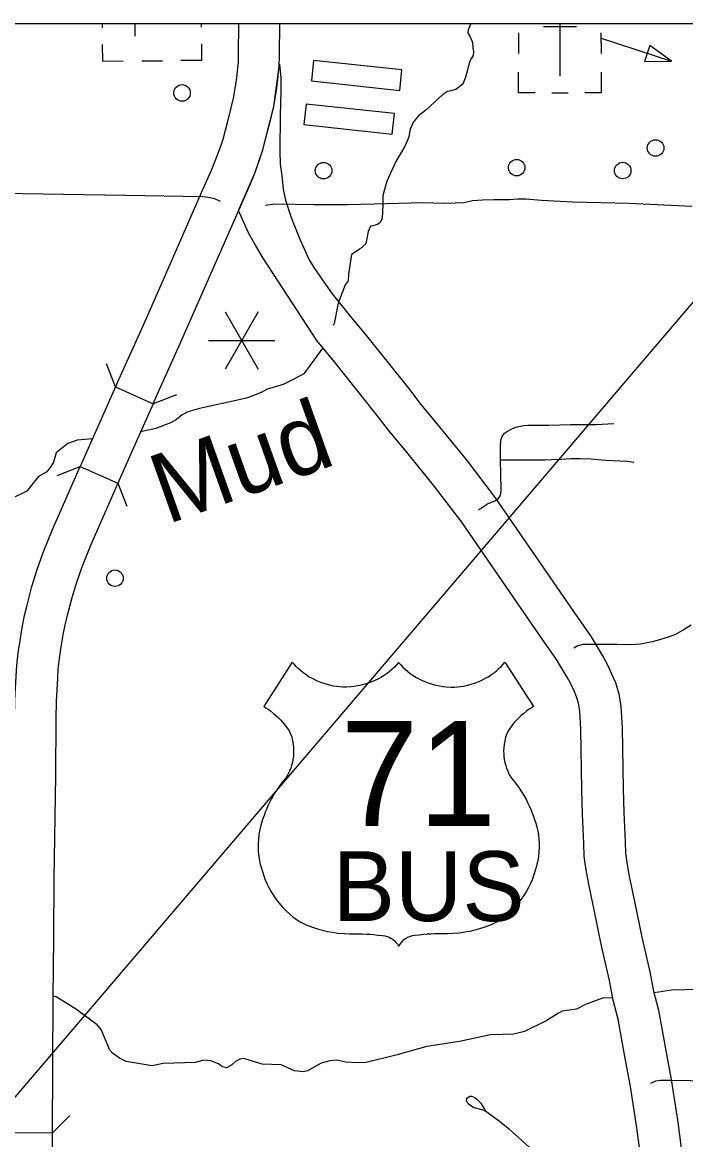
# Model space of a CAD drawing. Extents: x 1382482 to 1385815, y 1168351 to 1170484.
# Drawn here: x 1384330.9 to 1384491.5, y 1169309.6 to 1169580 of the extents above; entities that cross this region are included whole.
import ezdxf

# ---------------------------------------------------------------- set-up
doc = ezdxf.new("R2010")
doc.units = 0
for name, color, linetype in [('10', 7, 'Continuous'), ('15', 7, 'Continuous'), ('22', 7, 'Continuous'), ('35', 7, 'Continuous'), ('37', 7, 'Continuous'), ('48', 7, 'Continuous'), ('57', 7, 'Continuous'), ('Default', 7, 'Continuous'), ('R_Dimension', 7, 'Continuous'), ('R_No Plot', 7, 'Continuous')]:
    doc.layers.add(name, color=color, linetype=linetype)

msp = doc.modelspace()

# ---------------------------------------------------------------- linework, layer by layer
at = {"layer": '10'}
for points in [[(1384383.23, 1169534.42), (1384387.14, 1169543.49), (1384389.03, 1169548.84), (1384391.74, 1169559.61), (1384393.11, 1169569.87), (1384393.48, 1169566.57), (1384393.48, 1169563.3), (1384393.33, 1169557.39), (1384393.24, 1169548.76), (1384393.33, 1169545.62), (1384393.68, 1169542.87), (1384394.04, 1169539.57), (1384394.61, 1169536.9), (1384395.96, 1169532.72), (1384398.07, 1169527.54), (1384400.3, 1169522.48), (1384401.48, 1169520.67), (1384403.64, 1169517.52), (1384405.93, 1169514.26), (1384409.6, 1169509.67), (1384409.86, 1169509.35)], [(1384402.15, 1169502.98), (1384389.22, 1169522.94), (1384387.39, 1169525.88), (1384385.69, 1169528.89), (1384384.49, 1169531.54), (1384383.23, 1169534.42)], [(1384409.86, 1169509.35), (1384414.2, 1169504.11), (1384424.35, 1169491.44), (1384427.36, 1169487.53), (1384432.01, 1169481.88), (1384438.54, 1169473.85), (1384445.39, 1169464.94), (1384464.29, 1169437.42), (1384468.6, 1169431.26), (1384471.58, 1169426.28), (1384472.51, 1169424.53), (1384473.55, 1169422.34), (1384474.48, 1169420.2), (1384475.27, 1169417.52), (1384475.8, 1169414.44), (1384476.06, 1169409.29), (1384476.3, 1169394.54), (1384476.49, 1169388.81), (1384476.82, 1169381.66), (1384476.91, 1169378.96), (1384477.11, 1169377.28), (1384477.38, 1169375.76), (1384477.74, 1169373.73), (1384478.45, 1169370.33), (1384479.08, 1169367.26), (1384480.89, 1169358.63), (1384482.81, 1169350.2), (1384483.71, 1169345.55), (1384484.87, 1169340.95), (1384485.71, 1169336.52), (1384486.77, 1169330.7), (1384487.98, 1169324.16), (1384489.59, 1169313.88), (1384490.38, 1169307.55)], [(1384480.43, 1169306.53), (1384479.68, 1169312.48), (1384478.12, 1169322.48), (1384476.94, 1169328.9), (1384475.88, 1169334.69), (1384475.1, 1169338.8), (1384473.95, 1169343.38), (1384473.03, 1169348.13), (1384471.12, 1169356.49), (1384469.28, 1169365.24), (1384468.66, 1169368.31), (1384467.93, 1169371.82), (1384467.53, 1169374.02), (1384467.21, 1169375.85), (1384466.93, 1169378.2), (1384466.83, 1169381.26), (1384466.5, 1169388.41), (1384466.3, 1169394.29), (1384466.06, 1169408.96), (1384465.84, 1169413.34), (1384465.51, 1169415.25), (1384465.06, 1169416.79), (1384464.45, 1169418.2), (1384463.57, 1169420.04), (1384462.87, 1169421.37), (1384460.2, 1169425.82), (1384456.07, 1169431.72), (1384437.3, 1169459.06), (1384430.7, 1169467.64), (1384424.27, 1169475.54), (1384419.53, 1169481.31), (1384416.49, 1169485.27), (1384406.45, 1169497.79), (1384402.15, 1169502.98)]]:
    msp.add_lwpolyline(points, dxfattribs=at)
at = {"layer": '15'}
for points in [[(1384383.23, 1169579.7), (1384383.15, 1169572.16), (1384383.11, 1169570.02), (1384383.08, 1169569.78), (1384382.82, 1169567.21), (1384382.53, 1169564.96), (1384381.94, 1169561.64), (1384381.39, 1169559.29), (1384380.59, 1169555.99), (1384379.43, 1169551.65), (1384378.97, 1169550.2), (1384378.17, 1169548.07), (1384377.84, 1169547.17), (1384376.57, 1169544.12), (1384374.2, 1169538.72), (1384364.4, 1169516.4), (1384359.63, 1169505.56), (1384354.2, 1169493.43), (1384353.44, 1169491.74), (1384362.57, 1169487.66)], [(1384362.57, 1169487.66), (1384363.32, 1169489.34), (1384368.77, 1169501.51), (1384373.56, 1169512.38), (1384383.36, 1169534.7), (1384385.77, 1169540.19), (1384387.14, 1169543.49), (1384387.54, 1169544.57), (1384388.42, 1169546.94), (1384389.03, 1169548.84), (1384390.28, 1169553.53), (1384391.11, 1169556.97), (1384391.74, 1169559.61), (1384392.42, 1169563.44), (1384392.76, 1169566.08), (1384393.01, 1169568.65), (1384393.09, 1169569.27), (1384393.15, 1169572.01), (1384393.23, 1169579.7)], [(1384353.44, 1169491.74), (1384349.32, 1169482.51), (1384344.9, 1169472.5)], [(1384362.57, 1169487.66), (1384358.46, 1169478.45), (1384354.05, 1169468.46)], [(1384338.14, 1169311.22), (1384328.14, 1169311.27), (1384328.32, 1169344.04), (1384328.45, 1169358.54), (1384328.5, 1169373.03), (1384328.95, 1169397.67), (1384329.04, 1169411.52), (1384329.08, 1169416.04), (1384329.38, 1169421.73), (1384329.53, 1169424.34), (1384329.9, 1169427.4), (1384330.37, 1169430.41), (1384330.88, 1169433.52), (1384331.42, 1169436.43), (1384332, 1169438.62), (1384333.21, 1169443.46), (1384334.5, 1169447.58), (1384335.93, 1169451.66), (1384338.18, 1169457.24), (1384342.61, 1169467.31), (1384344.9, 1169472.5)], [(1384344.9, 1169472.5), (1384354.05, 1169468.46), (1384351.76, 1169463.28), (1384347.39, 1169453.36), (1384345.29, 1169448.15), (1384344, 1169444.43), (1384342.84, 1169440.75), (1384341.69, 1169436.12), (1384341.18, 1169434.23), (1384340.73, 1169431.79), (1384340.24, 1169428.83), (1384339.81, 1169426.03), (1384339.49, 1169423.46), (1384339.37, 1169421.19), (1384339.08, 1169415.73), (1384339.04, 1169411.44), (1384338.95, 1169397.54), (1384338.5, 1169372.92), (1384338.45, 1169358.48), (1384338.32, 1169343.96), (1384338.14, 1169311.22)], [(1384338.14, 1169311.22), (1384338.09, 1169302.22)]]:
    msp.add_lwpolyline(points, dxfattribs=at)
at = {"layer": '22'}
for points in [[(1384421.98, 1169425.08), (1384421.46, 1169424.49), (1384420.95, 1169423.97), (1384420.38, 1169423.43), (1384419.77, 1169422.91), (1384419.17, 1169422.44), (1384418.45, 1169421.94), (1384417.67, 1169421.45), (1384416.79, 1169420.97), (1384415.67, 1169420.45), (1384414.81, 1169420.12), (1384413.84, 1169419.8), (1384412.95, 1169419.57), (1384412.13, 1169419.4), (1384411.26, 1169419.27), (1384410.47, 1169419.18), (1384409.38, 1169419.13), (1384408.5, 1169419.14), (1384407.73, 1169419.19), (1384406.99, 1169419.27), (1384406.25, 1169419.38), (1384405.32, 1169419.57), (1384404.45, 1169419.8), (1384403.4, 1169420.14), (1384402.51, 1169420.49), (1384401.7, 1169420.86), (1384400.96, 1169421.25), (1384400.27, 1169421.65), (1384399.51, 1169422.16), (1384398.81, 1169422.67), (1384398.2, 1169423.17), (1384397.69, 1169423.62), (1384397.17, 1169424.12), (1384396.66, 1169424.66), (1384396.25, 1169425.13), (1384389.32, 1169414.43), (1384389.82, 1169414.13), (1384390.41, 1169413.75), (1384390.96, 1169413.35), (1384391.71, 1169412.77), (1384392.3, 1169412.26), (1384392.83, 1169411.77), (1384393.36, 1169411.22), (1384393.91, 1169410.61), (1384394.31, 1169410.14), (1384394.7, 1169409.64), (1384395.09, 1169409.09), (1384395.47, 1169408.51), (1384395.83, 1169407.83), (1384396.1, 1169406.99), (1384396.3, 1169406.16), (1384396.45, 1169405.28), (1384396.54, 1169404.46), (1384396.56, 1169403.67), (1384396.54, 1169402.93), (1384396.5, 1169402.33), (1384396.4, 1169401.6), (1384396.26, 1169400.91), (1384396.07, 1169400.17), (1384395.86, 1169399.52), (1384395.58, 1169398.79), (1384395.12, 1169397.85), (1384394.66, 1169397.11), (1384394.11, 1169396.44), (1384393.43, 1169395.57), (1384392.88, 1169394.8), (1384392.37, 1169394.04), (1384391.89, 1169393.29), (1384391.5, 1169392.62), (1384391.15, 1169391.99), (1384390.76, 1169391.24), (1384390.34, 1169390.37), (1384389.97, 1169389.52), (1384389.71, 1169388.88), (1384389.4, 1169388.07), (1384389.06, 1169387.07), (1384388.8, 1169386.24), (1384388.55, 1169385.34), (1384388.31, 1169384.28), (1384388.16, 1169383.35), (1384388.05, 1169382.37), (1384387.98, 1169381.31), (1384387.98, 1169380.31), (1384388.02, 1169379.33), (1384388.14, 1169378.18), (1384388.32, 1169377.09), (1384388.5, 1169376.27), (1384388.69, 1169375.55), (1384388.93, 1169374.73), (1384389.24, 1169373.71), (1384389.7, 1169372.48), (1384390.09, 1169371.57), (1384390.55, 1169370.64), (1384391.05, 1169369.72), (1384391.7, 1169368.67), (1384392.38, 1169367.7), (1384393.03, 1169366.86), (1384393.77, 1169366), (1384394.73, 1169365.01), (1384395.54, 1169364.26), (1384396.38, 1169363.56)], [(1384421.98, 1169425.08), (1384422.51, 1169424.49), (1384423.01, 1169423.97), (1384423.58, 1169423.43), (1384424.2, 1169422.91), (1384424.8, 1169422.44), (1384425.52, 1169421.94), (1384426.29, 1169421.45), (1384427.18, 1169420.97), (1384428.3, 1169420.45), (1384429.16, 1169420.12), (1384430.13, 1169419.8), (1384431.02, 1169419.57), (1384431.84, 1169419.4), (1384432.7, 1169419.27), (1384433.5, 1169419.18), (1384434.59, 1169419.13), (1384435.47, 1169419.14), (1384436.24, 1169419.19), (1384436.97, 1169419.27), (1384437.71, 1169419.38), (1384438.65, 1169419.57), (1384439.51, 1169419.8), (1384440.57, 1169420.14), (1384441.46, 1169420.49), (1384442.27, 1169420.86), (1384443.01, 1169421.25), (1384443.69, 1169421.65), (1384444.46, 1169422.16), (1384445.16, 1169422.67), (1384445.77, 1169423.17), (1384446.28, 1169423.62), (1384446.8, 1169424.12), (1384447.31, 1169424.66), (1384447.72, 1169425.13), (1384454.64, 1169414.43), (1384454.15, 1169414.13), (1384453.56, 1169413.75), (1384453, 1169413.35), (1384452.26, 1169412.77), (1384451.67, 1169412.26), (1384451.14, 1169411.77), (1384450.6, 1169411.22), (1384450.05, 1169410.61), (1384449.66, 1169410.14), (1384449.27, 1169409.64), (1384448.88, 1169409.09), (1384448.49, 1169408.51), (1384448.14, 1169407.83), (1384447.87, 1169406.99), (1384447.67, 1169406.16), (1384447.51, 1169405.28), (1384447.43, 1169404.46), (1384447.4, 1169403.67), (1384447.42, 1169402.93), (1384447.47, 1169402.33), (1384447.57, 1169401.6), (1384447.7, 1169400.91), (1384447.9, 1169400.17), (1384448.11, 1169399.52), (1384448.39, 1169398.79), (1384448.84, 1169397.85), (1384449.3, 1169397.11), (1384449.86, 1169396.44), (1384450.54, 1169395.57), (1384451.09, 1169394.8), (1384451.6, 1169394.04), (1384452.07, 1169393.29), (1384452.47, 1169392.62), (1384452.82, 1169391.99), (1384453.2, 1169391.24), (1384453.62, 1169390.37), (1384454, 1169389.52), (1384454.26, 1169388.88), (1384454.56, 1169388.07), (1384454.9, 1169387.07), (1384455.17, 1169386.24), (1384455.42, 1169385.34), (1384455.65, 1169384.28), (1384455.81, 1169383.35), (1384455.92, 1169382.37), (1384455.98, 1169381.31), (1384455.99, 1169380.31), (1384455.94, 1169379.33), (1384455.82, 1169378.18), (1384455.65, 1169377.09), (1384455.47, 1169376.27), (1384455.28, 1169375.55), (1384455.04, 1169374.73), (1384454.72, 1169373.71), (1384454.27, 1169372.48), (1384453.87, 1169371.57), (1384453.42, 1169370.64), (1384452.91, 1169369.72), (1384452.26, 1169368.67), (1384451.59, 1169367.7), (1384450.94, 1169366.86), (1384450.19, 1169366), (1384449.24, 1169365.01), (1384448.42, 1169364.26), (1384447.59, 1169363.56)], [(1384396.38, 1169363.56), (1384397.25, 1169362.9), (1384398.29, 1169362.22), (1384399.6, 1169361.63), (1384401.13, 1169361.04), (1384402.38, 1169360.64), (1384403.51, 1169360.32), (1384404.78, 1169360.03), (1384405.98, 1169359.81), (1384407.26, 1169359.63), (1384408.88, 1169359.49), (1384410.12, 1169359.45), (1384411.18, 1169359.46), (1384412.21, 1169359.45), (1384413.24, 1169359.41), (1384414.22, 1169359.37), (1384415.07, 1169359.31), (1384415.91, 1169359.24), (1384416.99, 1169359.13), (1384418.04, 1169358.99), (1384418.67, 1169358.91), (1384419.19, 1169358.8), (1384419.82, 1169358.54), (1384420.18, 1169358.34), (1384420.5, 1169358.14), (1384420.93, 1169357.79), (1384421.34, 1169357.37), (1384421.68, 1169356.94), (1384421.98, 1169356.44)], [(1384447.59, 1169363.56), (1384446.72, 1169362.9), (1384445.68, 1169362.22), (1384444.37, 1169361.63), (1384442.84, 1169361.04), (1384441.58, 1169360.64), (1384440.46, 1169360.32), (1384439.18, 1169360.03), (1384437.99, 1169359.81), (1384436.7, 1169359.63), (1384435.09, 1169359.49), (1384433.85, 1169359.45), (1384432.79, 1169359.46), (1384431.76, 1169359.45), (1384430.73, 1169359.41), (1384429.75, 1169359.37), (1384428.89, 1169359.31), (1384428.05, 1169359.24), (1384426.98, 1169359.13), (1384425.93, 1169358.99), (1384425.3, 1169358.91), (1384424.78, 1169358.8), (1384424.15, 1169358.54), (1384423.78, 1169358.34), (1384423.47, 1169358.14), (1384423.04, 1169357.79), (1384422.63, 1169357.37), (1384422.29, 1169356.94), (1384421.98, 1169356.44)]]:
    msp.add_lwpolyline(points, dxfattribs=at)
at = {"layer": '35'}
for points in [[(1384439.49, 1169579.7), (1384438.84, 1169578.15), (1384438.71, 1169577.41), (1384439.27, 1169576.43), (1384439.87, 1169575.09), (1384439.96, 1169573.69), (1384440.1, 1169572.9), (1384440.01, 1169571.93), (1384439.5, 1169571.04), (1384439.22, 1169570.56), (1384438.21, 1169566.71), (1384437.5, 1169564.99), (1384435.83, 1169563.7), (1384434.66, 1169563.37), (1384433.78, 1169563.19), (1384432.62, 1169562.39), (1384430.71, 1169560.77), (1384429.55, 1169559.61), (1384428.53, 1169558.72), (1384426.76, 1169557.37), (1384425.56, 1169555.93), (1384424.81, 1169554.12), (1384424.44, 1169552.35), (1384424.23, 1169551.59), (1384423.44, 1169549.82), (1384421.3, 1169546.29), (1384419.12, 1169541.5), (1384418.14, 1169538.06), (1384418.19, 1169536.24), (1384418.17, 1169536.13)], [(1384418.19, 1169536.24), (1384418.05, 1169533.65), (1384417.91, 1169532.44), (1384417.49, 1169531.51), (1384416.84, 1169531.04), (1384415.77, 1169530.76), (1384415.21, 1169530.62), (1384414.61, 1169529.37), (1384414.07, 1169526.36), (1384412.66, 1169525.14), (1384410.61, 1169523.79), (1384409.87, 1169519.06), (1384409.73, 1169517.43), (1384409.03, 1169516.45), (1384407.38, 1169512.04), (1384406.37, 1169507.12), (1384406.12, 1169506.59)], [(1384403.63, 1169501.2), (1384399.03, 1169494.94), (1384396.31, 1169493.43), (1384394.04, 1169492.36), (1384390.18, 1169491.2)], [(1384390.18, 1169491.2), (1384388.74, 1169490.41), (1384385.39, 1169489.1), (1384383.36, 1169488.64), (1384373.82, 1169486.5), (1384370.94, 1169485.76), (1384369.59, 1169484.97), (1384368.24, 1169483.9), (1384366.76, 1169483.06), (1384363.22, 1169481.72), (1384359.54, 1169480.87)], [(1384347.86, 1169479.21), (1384344.15, 1169478.84), (1384341.94, 1169478.1), (1384340.29, 1169476.77), (1384339.07, 1169475.82), (1384338.47, 1169473.57), (1384337.82, 1169472.53), (1384336.84, 1169471.22), (1384334.82, 1169470.09), (1384333.42, 1169468.4), (1384331.95, 1169466.52), (1384328.35, 1169464.72)], [(1384494.37, 1169345.96), (1384488.05, 1169345.82), (1384483.8, 1169345.19)], [(1384460.69, 1169340.25), (1384457.87, 1169338.47), (1384452.46, 1169335.79), (1384449.91, 1169335.14), (1384444.22, 1169335.02), (1384436.69, 1169333.36), (1384428.81, 1169332.15), (1384421.29, 1169330.1), (1384414.12, 1169328.33), (1384412.01, 1169328.19), (1384409.22, 1169328.41), (1384407.06, 1169328.88), (1384405.31, 1169328.71), (1384403.24, 1169328.13), (1384399.94, 1169326.31), (1384398.87, 1169326.02), (1384396.76, 1169326.25), (1384393.56, 1169327.74), (1384388.93, 1169327.87), (1384384.54, 1169329.28), (1384383.58, 1169329.11), (1384382.51, 1169328.51), (1384381.6, 1169327.7), (1384380.33, 1169327.01), (1384379.37, 1169327.28), (1384378.37, 1169328), (1384376.49, 1169328.7), (1384374.74, 1169328.89), (1384372.79, 1169328.32), (1384365.01, 1169328.06), (1384362.31, 1169327.52), (1384356, 1169328.56), (1384354.4, 1169329.35), (1384352.76, 1169330.53), (1384352.08, 1169331.25), (1384349.97, 1169336.27), (1384349.05, 1169337.43), (1384344, 1169341.15), (1384339.08, 1169344.19), (1384338.32, 1169344.38)], [(1384473.86, 1169343.83), (1384471.56, 1169343.91), (1384467.21, 1169342.37), (1384465.02, 1169341.2), (1384461.56, 1169340.7), (1384460.69, 1169340.25)]]:
    msp.add_lwpolyline(points, dxfattribs=at)
at = {"layer": '37'}
for points in [[(1384353.44, 1169491.74), (1384351.3, 1169497.34)], [(1384368.18, 1169489.8), (1384362.57, 1169487.66)], [(1384339.3, 1169470.34), (1384344.9, 1169472.5)], [(1384354.05, 1169468.46), (1384356.21, 1169462.87)], [(1384342.4, 1169315.44), (1384338.14, 1169311.22)]]:
    msp.add_lwpolyline(points, dxfattribs=at)
at = {"layer": '48'}
for p, q in [((1384387.99, 1169509.89), (1384379.99, 1169496.03)), ((1384379.99, 1169509.89), (1384387.99, 1169496.03)), ((1384375.99, 1169502.96), (1384391.99, 1169502.96))]:
    msp.add_line(p, q, dxfattribs=at)
at = {"layer": '57'}
for p, q in [((1384350.22, 1169579.7), (1384350.23, 1169578.6)), ((1384358.25, 1169576.64), (1384358.23, 1169579.7)), ((1384374.23, 1169578.77), (1384374.23, 1169579.7)), ((1384457.02, 1169578.92), (1384465.05, 1169578.92)), ((1384461.02, 1169579.7), (1384461.02, 1169566.92)), ((1384451.02, 1169577.39), (1384451.02, 1169572.39)), ((1384471.02, 1169574.92), (1384471.02, 1169577.39)), ((1384461.02, 1169574.92), (1384461.02, 1169574.92)), ((1384461.02, 1169574.92), (1384461.02, 1169574.92)), ((1384471.02, 1169574.92), (1384471.02, 1169572.39)), ((1384359.83, 1169570.65), (1384364.83, 1169570.68)), ((1384401.4, 1169570.75), (1384400.86, 1169565.78)), ((1384422.78, 1169568.44), (1384401.4, 1169570.75)), ((1384422.24, 1169563.47), (1384422.78, 1169568.44)), ((1384400.86, 1169565.78), (1384422.24, 1169563.47)), ((1384459.04, 1169562.92), (1384463.04, 1169562.92)), ((1384399.58, 1169560.2), (1384399.05, 1169555.23)), ((1384420.96, 1169557.89), (1384399.58, 1169560.2)), ((1384420.42, 1169552.92), (1384420.96, 1169557.89)), ((1384399.05, 1169555.23), (1384420.42, 1169552.92))]:
    msp.add_line(p, q, dxfattribs=at)
for points in [[(1384471.02, 1169576.15), (1384488, 1169570.53)], [(1384350.26, 1169574.58), (1384350.29, 1169570.58), (1384355.29, 1169570.62)], [(1384374.26, 1169574.75), (1384374.29, 1169570.75), (1384369.29, 1169570.72)], [(1384455.02, 1169562.92), (1384451.02, 1169562.92), (1384451.02, 1169567.92)], [(1384471.02, 1169567.92), (1384471.02, 1169562.92), (1384467.02, 1169562.92)]]:
    msp.add_lwpolyline(points, dxfattribs=at)
msp.add_lwpolyline([(1384482.83, 1169574.39), (1384481.54, 1169570.52), (1384488, 1169570.53)], close=True, dxfattribs=at)
at = {"layer": 'Default'}
for points in [[(1384281.75, 1169539.36), (1384288.28, 1169539.25), (1384317.49, 1169538.78), (1384325.98, 1169538.64), (1384355.7, 1169538.15), (1384374.64, 1169537.84), (1384376.36, 1169537.59), (1384377.38, 1169537.32), (1384378.78, 1169536.71)], [(1384492.97, 1169535.41), (1384477.77, 1169536.1), (1384464.06, 1169536.45), (1384456.59, 1169536.85), (1384452.77, 1169537.15), (1384450.84, 1169537.2), (1384448.8, 1169537.03), (1384445.01, 1169537.03), (1384442.27, 1169536.91), (1384439.87, 1169536.74), (1384437.77, 1169536.33), (1384435.67, 1169536.21), (1384432.76, 1169536.1), (1384427.97, 1169536.33), (1384416.09, 1169535.98), (1384409.67, 1169535.8), (1384401.51, 1169535.8), (1384392.07, 1169535.98), (1384389.77, 1169535.61)], [(1384441.35, 1169462), (1384443.49, 1169463.44), (1384445.28, 1169464.22), (1384446.09, 1169464.65), (1384446.52, 1169465.27), (1384446.76, 1169465.97), (1384446.83, 1169466.98), (1384446.67, 1169474.15), (1384446.64, 1169477.5), (1384446.72, 1169478.9), (1384447.03, 1169479.79), (1384447.65, 1169480.53), (1384448.31, 1169481.08), (1384449.52, 1169481.7), (1384450.69, 1169482.13), (1384452.28, 1169482.44), (1384453.25, 1169482.48), (1384458.31, 1169482.48), (1384463.59, 1169482.63), (1384469.78, 1169482.67), (1384474.1, 1169482.87)], [(1384446.67, 1169474.15), (1384451.65, 1169474.11), (1384455.38, 1169474.11), (1384457.45, 1169474.11), (1384459.08, 1169474.19), (1384461.42, 1169474.3), (1384463.63, 1169474.42), (1384465.93, 1169474.42), (1384468.58, 1169474.34), (1384472.04, 1169474.07), (1384475.54, 1169473.91), (1384477.37, 1169473.8), (1384478.93, 1169473.52)], [(1384492.8, 1169434.15), (1384491.08, 1169433.06), (1384489.02, 1169431.85), (1384487.46, 1169431.27), (1384485.17, 1169430.57), (1384483.32, 1169430.06), (1384482.17, 1169429.83), (1384480.57, 1169429.54), (1384478.28, 1169429.36), (1384474.78, 1169429.44), (1384466.58, 1169429.44), (1384465.34, 1169429.13), (1384464.4, 1169428.54)], [(1384483.05, 1169323.32), (1384484.24, 1169323.86), (1384485.35, 1169324.06), (1384487.73, 1169324.02), (1384492.54, 1169323.94), (1384502.85, 1169323.57), (1384507.32, 1169323.49)], [(1384485.83, 1169301.65), (1384480.21, 1169302.01), (1384469.44, 1169302.66), (1384464.54, 1169303.11), (1384461.99, 1169303.55), (1384460.17, 1169304.2), (1384457.91, 1169305.13), (1384455.48, 1169306.51), (1384453.7, 1169307.76), (1384450.88, 1169310.27), (1384448.86, 1169312.05), (1384446.1, 1169314.24), (1384444.28, 1169315.54), (1384443.03, 1169316.51)]]:
    msp.add_lwpolyline(points, dxfattribs=at)
msp.add_lwpolyline([(1384443.03, 1169316.51), (1384441.85, 1169316.95), (1384439.99, 1169317.44), (1384438.78, 1169318.33), (1384438.41, 1169319.1), (1384438.49, 1169319.71), (1384438.86, 1169319.95), (1384439.22, 1169320.15), (1384439.63, 1169320.15), (1384440.4, 1169319.83), (1384440.96, 1169319.34), (1384441.85, 1169318.45)], close=True, dxfattribs=at)
for centre in [(1384369.56, 1169562.89), (1384484.18, 1169549.55), (1384403.82, 1169544.08), (1384450.56, 1169544.81), (1384476.23, 1169544.1), (1384353.32, 1169445.47)]:
    msp.add_circle(centre, 2, dxfattribs=at)
at = {"layer": 'R_Dimension'}
msp.add_line((1384666.56, 1169715.52), (1384203.4, 1169172.61), dxfattribs=at)
at = {"layer": 'R_No Plot'}
msp.add_lwpolyline([(1383432.46, 1169579.7), (1384939.88, 1169579.7), (1384939.88, 1168702.36), (1383432.46, 1168702.36)], close=True, dxfattribs=at)

# ---------------------------------------------------------------- texts
at = {"layer": '22'}
for s, height, p in [('71', 25.344, (1384407.93, 1169385.56)), ('BUS', 16.896, (1384406.02, 1169362.52))]:
    msp.add_text(s, height=height, dxfattribs=at).set_placement(p)
at = {"layer": '35'}
msp.add_text('Mud', height=16.896, rotation=19.6308, dxfattribs=at).set_placement((1384365.89, 1169458.42))

doc.saveas('drawing.dxf')
